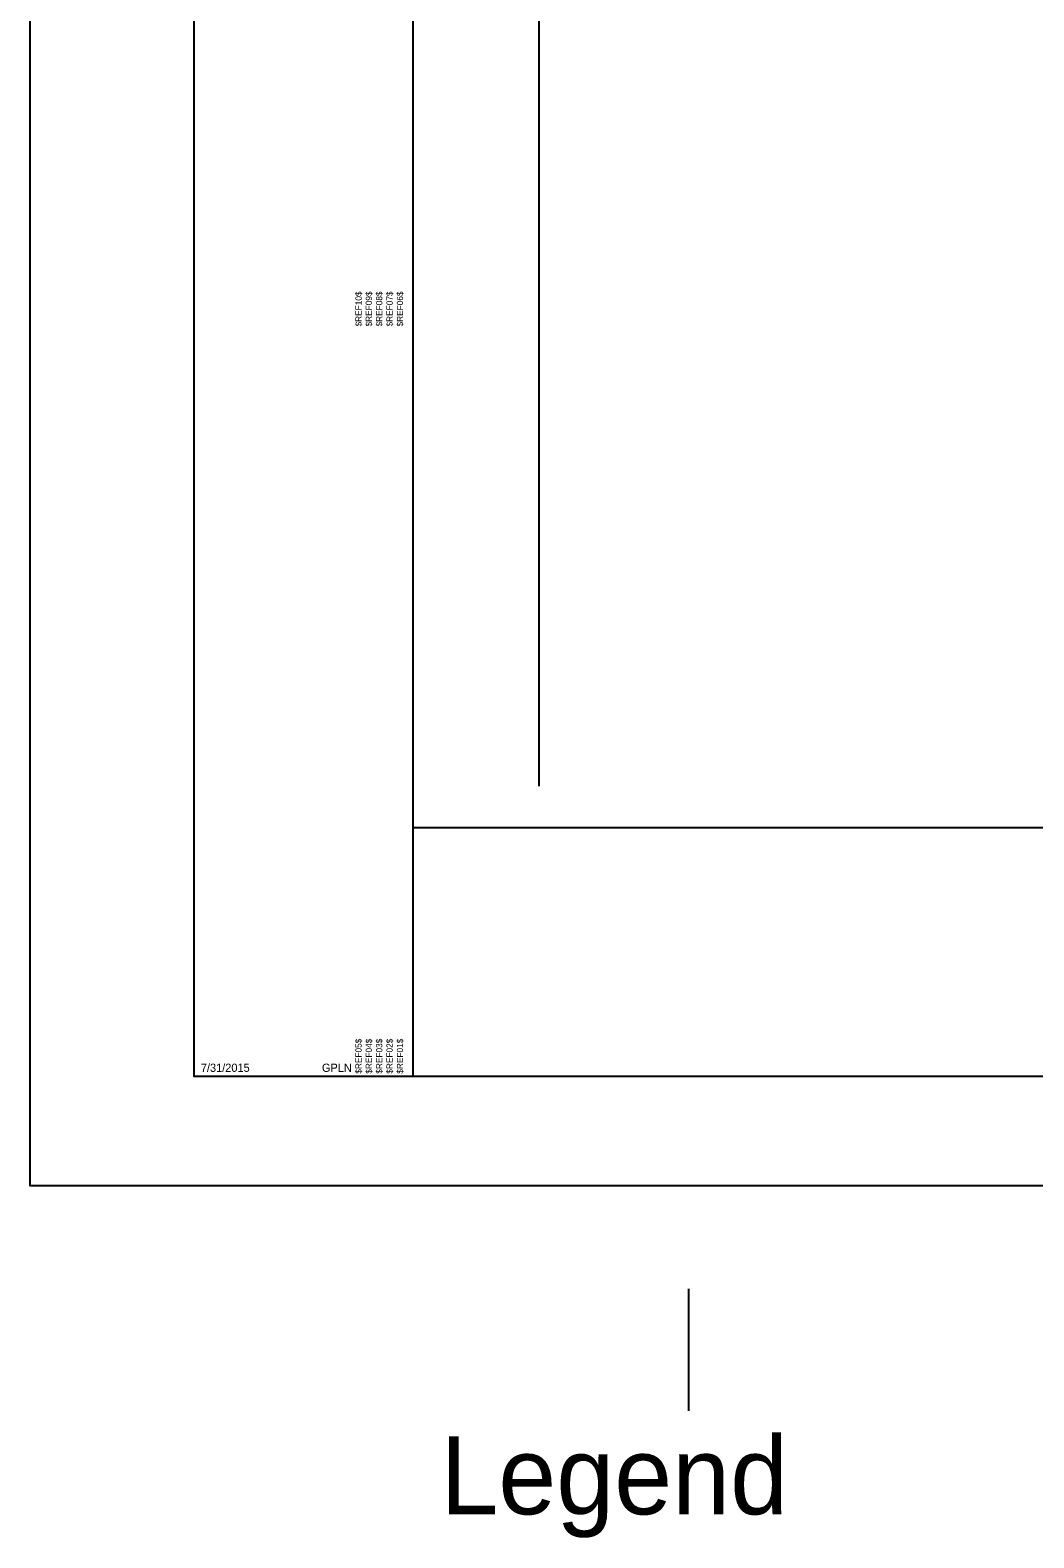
# Model space of a CAD drawing. Extents: x 2158280 to 2158980, y 1040586 to 1041166.
# Drawn here: x 2158279.6 to 2158463.1, y 1040587.7 to 1040863.5 of the extents above; entities that cross this region are included whole.
import ezdxf

# ---------------------------------------------------------------- set-up
doc = ezdxf.new("R2010")
doc.units = 0
for name, color, linetype in [('SHT_B_MainLine-Text', 7, 'Continuous'), ('SHT_B_Minor-Station-Tic-Line', 7, 'Continuous'), ('SHT_B_North-Arrow', 7, 'Continuous'), ('SHT_B_Plot-Sub-Text', 7, 'Continuous'), ('UTLE_E_UG-Wat-Line-30-Qual-B-50', 7, 'Continuous'), ('UTLE_E_UG-Wat-Line-30-Qual-C-50', 7, 'Continuous')]:
    doc.layers.add(name, color=color, linetype=linetype)

msp = doc.modelspace()

# ---------------------------------------------------------------- linework, layer by layer
at = {"layer": 'SHT_B_MainLine-Text'}
msp.add_line((2158372.56, 1041070), (2158372.56, 1040725.2), dxfattribs=at)
at = {"layer": 'SHT_B_North-Arrow'}
for p, q in [((2158349.56, 1041082.15), (2158349.56, 1040672.15)), ((2158349.56, 1040717.65), (2158969.56, 1040717.65)), ((2158359.56, 1040717.65), (2158359.56, 1040717.65)), ((2158359.56, 1040717.65), (2158359.56, 1040717.65)), ((2158359.56, 1040717.65), (2158359.56, 1040717.65)), ((2158400.02, 1040610.97), (2158400.02, 1040633.27))]:
    msp.add_line(p, q, dxfattribs=at)
at = {"layer": 'UTLE_E_UG-Wat-Line-30-Qual-B-50'}
msp.add_lwpolyline([(2158309.56, 1041092.15), (2158969.56, 1041092.15), (2158969.56, 1040672.15), (2158309.56, 1040672.15)], close=True, dxfattribs=at)
at = {"layer": 'UTLE_E_UG-Wat-Line-30-Qual-C-50'}
msp.add_lwpolyline([(2158279.56, 1041112.15), (2158979.56, 1041112.15), (2158979.56, 1040652.15), (2158279.56, 1040652.15)], close=True, dxfattribs=at)

# ---------------------------------------------------------------- texts
at = {"layer": 'SHT_B_Minor-Station-Tic-Line'}
for s, p in [('$REF10$', (2158340.18, 1040809.29)), ('$REF09$', (2158342.06, 1040809.29)), ('$REF08$', (2158343.96, 1040809.29)), ('$REF07$', (2158345.86, 1040809.29)), ('$REF06$', (2158347.76, 1040809.29)), ('$REF05$', (2158340.18, 1040672.63)), ('$REF04$', (2158342.06, 1040672.63)), ('$REF03$', (2158343.96, 1040672.63)), ('$REF02$', (2158345.86, 1040672.63)), ('$REF01$', (2158347.76, 1040672.63))]:
    msp.add_text(s, height=1.134, rotation=90.0013, dxfattribs=at).set_placement(p)
at = {"layer": 'SHT_B_North-Arrow'}
msp.add_text('Legend', height=14.25, rotation=0, dxfattribs=at).set_placement((2158354.58, 1040592.05))
at = {"layer": 'SHT_B_Plot-Sub-Text'}
for s, p in [('7/31/2015', (2158310.78, 1040672.97)), ('GPLN', (2158332.92, 1040672.97))]:
    msp.add_text(s, height=1.501, rotation=0, dxfattribs=at).set_placement(p)

doc.saveas('drawing.dxf')
